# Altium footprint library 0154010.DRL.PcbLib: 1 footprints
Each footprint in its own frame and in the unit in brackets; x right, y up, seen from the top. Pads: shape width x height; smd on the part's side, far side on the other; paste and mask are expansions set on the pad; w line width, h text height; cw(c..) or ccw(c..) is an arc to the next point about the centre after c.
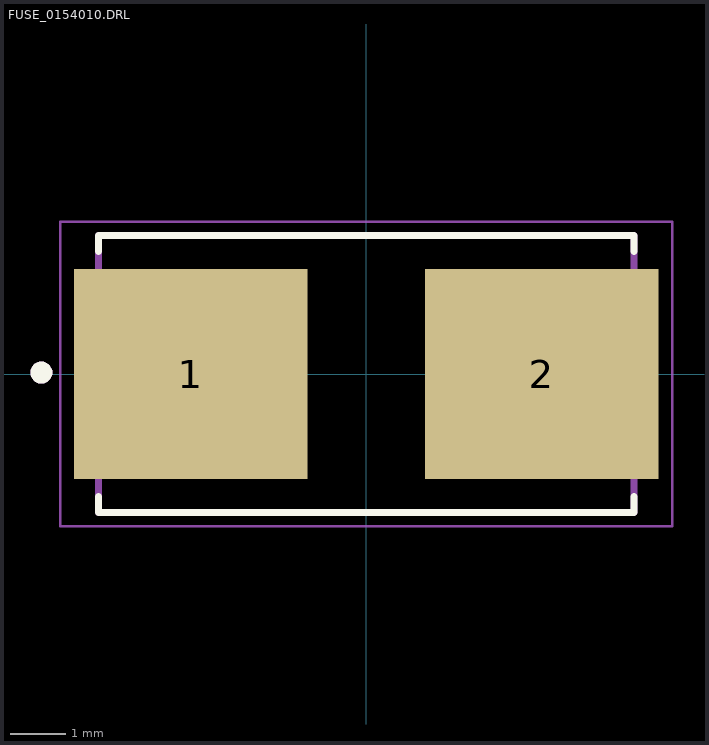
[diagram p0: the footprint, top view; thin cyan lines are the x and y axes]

## FUSE_0154010.DRL [mil]
height 150
pads (2):
  rect 167x150 smd: 1(-125.5,0) 2(125.5,0)
Top Overlay:
  circle w7.87: c-232.37,1 r3.94
  lines w5: -191.5,-87.6 -191.5,-99 191.5,-99 191.5,-87.6 ; -191.5,87.6 -191.5,99 191.5,99 191.5,87.6
Assembly Top:
  circle w7.87: c-232.37,1 r3.94
  lines w5: -191.5,-99 -191.5,99 191.5,99 191.5,-99 -191.5,-99
Courtyard Top:
  lines w1.97: -218.84,-108.84 218.84,-108.84 218.84,108.84 -218.84,108.84 -218.84,-108.84
3D body "step_temp.STEP": height 150, standoff 0, extent -191.54,-99.02 191.54,99.02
